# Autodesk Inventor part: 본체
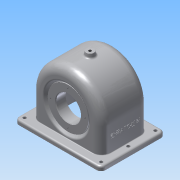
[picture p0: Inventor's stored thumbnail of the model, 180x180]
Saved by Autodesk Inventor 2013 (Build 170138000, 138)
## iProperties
Created: 2015-09
Part Number: 본체
Material: 알루미늄 6061
Document SubType Name: Modeling
Designer: Administrator
Density: 2.71 g/cm^3
Mass: 757.986 g
Surface Area: 938.987 cm^2
Volume: 279.7 cm^3
Author: Administrator
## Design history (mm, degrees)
sketch "스케치1"
  geometry: L1 (-57, -47)-(57, -47); L2 (57, -47)-(57, 0); L3 (-57, -47)-(-57, 0); A1 r 57 centre (0, 0) between (57, 0) and (-57, 0); 1 further point
  constraints: 6 end point, 2 coincident, 2 point on circle, 2 tangent, 1 centre point, 1 horizontal, 1 parallel, 1 perpendicular
  dimensions: "d0" = 47 distance from line of point (0, 0) L1; "d1" = 114 distance of L1.start L1.end
extrude "돌출1" new body sketch "스케치1" stored distance "d2" = 77; taper "d3" = 0 deg
sketch "스케치2"
  geometry: L1 (-6, 13.5)-(120, 13.5); L2 (127, 6.5)-(127, -83.5); L3 (120, -90.5)-(-6, -90.5); L4 (-13, -83.5)-(-13, 6.5); A1 r 7 centre (-6, 6.5) between (-6, 13.5) and (-13, 6.5); A2 r 7 centre (-6, -83.5) between (-13, -83.5) and (-6, -90.5); A3 r 7 centre (120, -83.5) between (120, -90.5) and (127, -83.5); A4 r 7 centre (120, 6.5) between (127, 6.5) and (120, 13.5); 6 further points
  constraints: 8 end point, 8 point on circle, 8 tangent, 6 point on line, 4 centre point, 3 equal radius, 2 midpoint, 2 parallel, 1 horizontal, 1 horizontal alignment, 1 perpendicular, 1 vertical alignment
  dimensions: "d4" = 104 distance of point (127, 13.5) point (127, -90.5); "d6" = 140 distance of point (127, -90.5) point (-13, -90.5); "d7" = 7 radius of A1
extrude "돌출2" join sketch "스케치2" distance "d8" = 7; taper "d9" = 0 deg
sketch "스케치3"
  geometry: C1 r 31 at (0, 0); 1 further point
  constraints: 1 centre point, 1 coincident
  dimensions: "d10" = 62 diameter of C1
extrude "돌출3" join sketch "스케치3" distance "d12" = 10; taper "d13" = 0 deg
sketch "스케치4"
  geometry: L1 (63, -47)-(-63, -47) reference; L2 (-51, 0)-(-51, -47); L3 (51, 0)-(51, -47); A1 r 57 centre (0, 0) between (57, 0) and (-57, 0) reference; A2 r 51 centre (0, 0) between (51, 0) and (-51, 0); 1 further point
  constraints: 4 end point, 2 point on circle, 2 point on line, 2 tangent, 1 centre point, 1 parallel, 1 perpendicular
  dimensions: "d14" = 6 radial gap between concentric circles of A1 A2
extrude "돌출4" cut sketch "스케치4" stored distance "d15" = 67; taper "d16" = 0 deg
sketch "스케치5"
  geometry: L1 (51, 33.5)-(0, 33.5) reference; L2 (0, 0)-(0, 33.5); L3 (0, 19.5)-(28, 19.5); L4 (28, 19.5)-(39.747, 33.5); L5 (57, 38.5)-(0, 38.5) reference
  constraints: 6 end point, 2 point on line, 1 perpendicular
  dimensions: "d17" = 56 diameter of L3.end L2; "d19" = 50 deg angle of L4 L3; "d21" = 19 distance between parallel lines of L3 L5
revolve "회전1" sketch "스케치5" stored, may be unused: angle "d22" = 90 deg
sketch "스케치6"
  geometry: L1 (0, 38.5)-(-40, 38.5) reference; L2 (57, 38.5)-(0, 38.5) reference; L3 (0, 0)-(0, 38.5); L4 (0, 35.5)-(33, 35.5); L5 (39.747, 33.5)-(28, 19.5) reference; L6 (37.416, 38.5)-(33.883, 34.29); L7 (33, 35.5)-(33, 34.611); A1 r 0.5 centre (33.5, 34.611) between (33, 34.611) and (33.883, 34.29); 1 further point
  constraints: 8 end point, 2 perpendicular, 2 point on circle, 2 point on line, 2 tangent, 1 centre point, 1 parallel
  dimensions: "d23" = 3 distance between parallel lines of L4 L2; "d25" = 5 distance between parallel lines of L5 L6; "d26" = 66 diameter of L7 L3; "d27" = 0.5 radius of A1
revolve "회전2" sketch "스케치6" stored, may be unused: angle "d28" = 90 deg
node "작업 평면2"
  node "작업 평면1"
sketch "스케치11"
  geometry: C1 r 6 at (0, 0); 1 further point
  constraints: 1 centre point, 1 coincident
  dimensions: "d81" = 12 diameter of C1
extrude "돌출5" join sketch "스케치11" distance "d83" = 10; taper "d84" = 10 deg
sketch "스케치7"
  geometry: A1 r 28 centre (0, 0) between (0, 28) and (0, -28); 3 further points
  constraints: 4 point on circle, 2 horizontal alignment, 2 vertical alignment, 1 centre point, 1 coincident
  dimensions: "d29" = 56 diameter of A1
hole "구멍1" sketch "스케치7" at (0, 28), (0, -28), (-28, 0), (28, 0) diameter "d31" = 2.459; stored, may be unused: countersink angle "d35" = 90 deg, drill point angle "d37" = 118 deg; dims "d32" = 7, "d33" = 4, "d34" = 2, "d36" = 9
sketch "스케치8"
  geometry: A1 r 24 centre (0, 0) between (0, 24) and (0, -24); 3 further points
  constraints: 4 point on circle, 2 horizontal alignment, 2 vertical alignment, 1 centre point, 1 coincident
  dimensions: "d38" = 48 diameter of A1
hole "구멍2" sketch "스케치8" at (0, 24), (0, -24), (-24, 0), (24, 0) diameter "d40" = 2.459; stored, may be unused: countersink angle "d44" = 90 deg, drill point angle "d46" = 118 deg; dims "d41" = 6, "d42" = 4, "d43" = 2, "d45" = 8
hole "구멍3" diameter "d49" = 40; stored, may be unused: countersink angle "d53" = 90 deg, drill point angle "d55" = 0 deg; dims "d47" = 10, "d48" = 10, "d50" = 6, "d51" = 4, "d52" = 2, "d54" = 16
hole "구멍4" diameter "d58" = 40; stored, may be unused: countersink angle "d62" = 90 deg, drill point angle "d64" = 0 deg; dims "d56" = 10, "d57" = 10, "d59" = 6, "d60" = 4, "d61" = 2, "d63" = 15
sketch "스케치9"
  geometry: 7 further points
  constraints: 4 horizontal alignment, 4 vertical alignment
  dimensions: "d65" = 124 distance of point (119, -38.5) point (-5, -38.5); "d67" = 62 distance of point (57, -38.5) point (-5, -38.5); "d68" = 44 distance of point (-5, -38.5) point (-5, -82.5); "d69" = 44 distance of point (-5, 5.5) point (-5, -38.5)
hole "구멍5" sketch "스케치9" at (-5, -38.5), (119, -38.5), (-5, -82.5), (-5, 5.5), (119, -82.5), (119, 5.5) diameter "d70" = 5; stored, may be unused: countersink angle "d74" = 90 deg, drill point angle "d76" = 0 deg; dims "d71" = 6, "d72" = 4, "d73" = 2, "d75" = 15
hole "구멍6" diameter "d87" = 4.459; stored, may be unused: countersink angle "d91" = 90 deg, drill point angle "d93" = 0 deg; dims "d85" = 10, "d86" = 10, "d88" = 12, "d89" = 4, "d90" = 2, "d92" = 15
sketch "스케치10"
  geometry: L1 (13.613, -31.061)-(63.387, -31.061); L2 (63.387, -31.061)-(63.387, -2.939); L3 (63.387, -2.939)-(13.613, -2.939); L4 (13.613, -2.939)-(13.613, -31.061); L5 (77, 0)-(0, 0) reference; L6 (-6.5, -40)-(83.5, -40) reference; L7 (0, -40)-(0, 0) reference; L8 (-6.5, -47)-(83.5, -47) reference; 7 further points
  constraints: 5 midpoint, 2 vertical alignment, 1 horizontal alignment, 2 other
  dimensions: "d105" = 30 distance from line of point (13.613, -17) L8
feature "엠보싱1" sketch "스케치10" dims "d0" = 47, "d1" = 114, "d78" = 0.5, "d79" = 0
chamfer "모따기1" distance "d94" = 1; stored, may be unused: second distance "d95" = 2, angle "d96" = 45 deg
fillet "모깎기1" dims "d97" = 14
fillet "모깎기2" dims "d98" = 9
fillet "모깎기4" dims "d100" = 3
fillet "모깎기5" dims "d101" = 3
fillet "모깎기7" dims "d103" = 3
fillet "모깎기8" dims "d104" = 1
node "솔리드1"
other parameters: "d80" = 6
